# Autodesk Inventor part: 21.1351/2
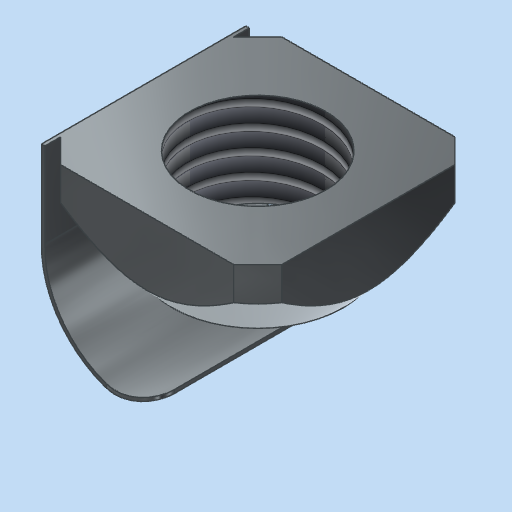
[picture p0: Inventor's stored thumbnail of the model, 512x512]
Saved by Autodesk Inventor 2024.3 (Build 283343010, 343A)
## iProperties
Created: 2006-12
Part Number: 21.1351/2
Document SubType Name: Modeling
Designer: Andy Moles
Material: Steel, Mild
Density: 7.85 g/cm^3
Mass: 4.24899 g
Surface Area: 8.34272 cm^2
Volume: 0.541273 cm^3
Description: M8 SQUARE NUT POS FXG
Vendor: S
Appearance: Zinc
Title: M8 SQUARE NUT POS FXG
Author: Andy Moles
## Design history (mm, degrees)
sketch "Sketch2"
  geometry: L1 (-5.086, -6.5)-(5.086, -6.5); L2 (6.5, -5.086)-(6.5, 5.086); L3 (5.086, 6.5)-(-5.086, 6.5); L4 (-6.5, 5.086)-(-6.5, -5.086); L5 (-6.5, 6.5)-(6.5, -6.5); L6 (5.086, 6.5)-(6.5, 5.086); L7 (0, -6.5)-(0, 6.5); L8 (-6.5, 0)-(6.5, 0); L9 (-5.086, 6.5)-(-6.5, 5.086); L10 (-5.086, -6.5)-(-6.5, -5.086); L11 (5.086, -6.5)-(6.5, -5.086); C1 r 4 at (0, 0); 2 further points
  constraints: 22 end point, 6 symmetric about line, 4 parallel, 3 midpoint, 2 coincident, 2 perpendicular, 1 centre point, 1 horizontal
  dimensions: "THREAD" = 8 diameter of C1; "d3" = 45 deg angle of L3 L6 (derived); "d4" = 2 distance of L3.start L2.end
extrude "Extrusion1" new body sketch "Sketch2" distance "d5" = 5.5; taper "d6" = 0 deg
workplane "Work Plane1"
sketch "Sketch4"
  geometry: L1 (12.192, 0)-(4.192, 0) reference; L2 (8.192, 0)-(13.192, 0); L3 (16.385, 5.5)-(16.385, 3.5); L4 (13.192, 0)-(16.797, 3.952); L5 (13.192, 0)-(16.385, 0); L6 (16.385, 3.5)-(16.385, 0); L7 (16.797, 3.952)-(16.797, -0.412); L8 (16.797, -0.412)-(13.192, -0.412); L9 (13.192, -0.412)-(13.192, 0); L10 (8.192, 5.5)-(8.192, 0); L11 (16.385, 5.5)-(16.385, 0) reference; L12 (16.385, 3.5)-(17.502, 3.5); L13 (9.192, 5.5)-(16.385, 5.5) reference
  constraints: 20 end point, 6 perpendicular, 1 collinear, 1 midpoint, 1 parallel, 1 point on line
  dimensions: "d10" = 5 distance of L2.start L2.end; "d15" = 2 distance between parallel lines of L12 L13
revolve "Revolution1" sketch "Sketch4" stored, may be unused: angle "d12" = 90 deg
thread "Thread1" dims "d13" = 10, "d14" = 0
sketch "Sketch6"
  geometry: L1 (2.954, -2.535)-(2.954, 6.006); L2 (2.954, -2.535)-(2.954, -7.535); L3 (2.954, -2.535)-(3.154, -2.535); L4 (3.154, -2.535)-(3.154, -7.535); L5 (-2.646, -13.135)-(-2.646, -13.335); L6 (2.954, 0)-(2.954, -1.933); L7 (-8.632, -2.535)-(1.539, -2.535) reference; L8 (2.954, -2.535)-(2.954, -4.468) reference; A1 r 5.374 centre (-2.416, -7.766) between (-2.646, -13.135) and (2.954, -7.535); A2 r 5.574 centre (-2.416, -7.766) between (-2.646, -13.335) and (3.154, -7.535); 4 further points; 1 other entity
  constraints: 12 end point, 4 point on circle, 3 collinear, 2 centre point, 2 horizontal, 2 parallel, 2 perpendicular, 1 coincident, 3 other
  dimensions: "d25" = 5 distance of L1.start L2.end; "d23" = 0.2 distance of L1.start L3.end; "d22" = 0.2 distance of L5.start L5.end; "d21" = 10.8 distance from line of L5.end L3; "d24" = 5.37434 radius of A1
extrude "Extrusion3" join sketch "Sketch6" taper "d27" = 0 deg; stored distance "d28" = 12
fillet "Fillet2" dims "d29" = 2
body "Solid1"
